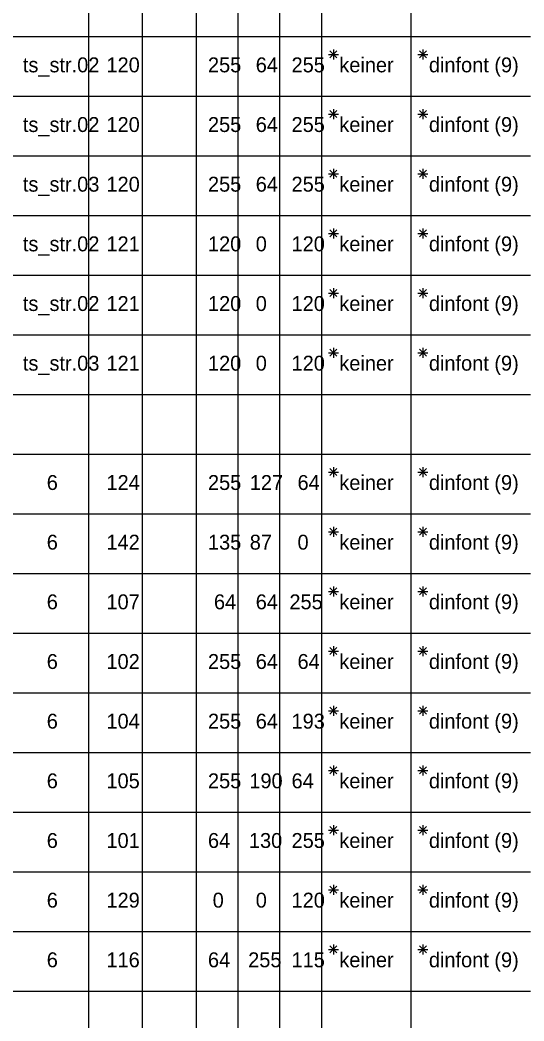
# Model space of a CAD drawing. Extents: x -29 to 48, y -113 to 16.
# Drawn here: x 23.45 to 31.89, y -47.5 to -30.72 of the extents above; entities that cross this region are included whole.
import ezdxf

# ---------------------------------------------------------------- set-up
doc = ezdxf.new("R2010")
doc.units = 0
doc.layers.add('Default', color=7, linetype='Continuous')

msp = doc.modelspace()

# ---------------------------------------------------------------- linework, layer by layer
at = {"layer": 'Default'}
for p, q in [((24.6, -0.7), (24.6, -89)), ((25.5, -0.7), (25.5, -89)), ((26.4, -0.7), (26.4, -89)), ((28.5, -0.7), (28.5, -96)), ((30, -0.7), (30, -96)), ((27.1, -1.5), (27.1, -89)), ((27.8, -1.5), (27.8, -89)), ((0, -31), (32, -31)), ((28.616, -31.3), (28.784, -31.3)), ((28.641, -31.241), (28.759, -31.359)), ((28.759, -31.241), (28.641, -31.359)), ((28.7, -31.216), (28.7, -31.384)), ((30.116, -31.3), (30.284, -31.3)), ((30.141, -31.241), (30.259, -31.359)), ((30.259, -31.241), (30.141, -31.359)), ((30.2, -31.216), (30.2, -31.384)), ((0, -32), (32, -32)), ((28.616, -32.3), (28.784, -32.3)), ((28.641, -32.241), (28.759, -32.359)), ((28.759, -32.241), (28.641, -32.359)), ((28.7, -32.216), (28.7, -32.384)), ((30.116, -32.3), (30.284, -32.3)), ((30.141, -32.241), (30.259, -32.359)), ((30.259, -32.241), (30.141, -32.359)), ((30.2, -32.216), (30.2, -32.384)), ((0, -33), (32, -33)), ((28.7, -33.216), (28.7, -33.384)), ((30.2, -33.216), (30.2, -33.384)), ((28.616, -33.3), (28.784, -33.3)), ((28.641, -33.241), (28.759, -33.359)), ((28.759, -33.241), (28.641, -33.359)), ((30.116, -33.3), (30.284, -33.3)), ((30.141, -33.241), (30.259, -33.359)), ((30.259, -33.241), (30.141, -33.359)), ((0, -34), (32, -34)), ((28.7, -34.216), (28.7, -34.384)), ((30.2, -34.216), (30.2, -34.384)), ((28.616, -34.3), (28.784, -34.3)), ((28.641, -34.241), (28.759, -34.359)), ((28.759, -34.241), (28.641, -34.359)), ((30.116, -34.3), (30.284, -34.3)), ((30.141, -34.241), (30.259, -34.359)), ((30.259, -34.241), (30.141, -34.359)), ((0, -35), (32, -35)), ((28.7, -35.216), (28.7, -35.384)), ((30.2, -35.216), (30.2, -35.384)), ((28.616, -35.3), (28.784, -35.3)), ((28.641, -35.241), (28.759, -35.359)), ((28.759, -35.241), (28.641, -35.359)), ((30.116, -35.3), (30.284, -35.3)), ((30.141, -35.241), (30.259, -35.359)), ((30.259, -35.241), (30.141, -35.359)), ((0, -36), (32, -36)), ((28.7, -36.216), (28.7, -36.384)), ((30.2, -36.216), (30.2, -36.384)), ((28.616, -36.3), (28.784, -36.3)), ((28.641, -36.241), (28.759, -36.359)), ((28.759, -36.241), (28.641, -36.359)), ((30.116, -36.3), (30.284, -36.3)), ((30.141, -36.241), (30.259, -36.359)), ((30.259, -36.241), (30.141, -36.359)), ((0, -37), (32, -37)), ((0, -38), (32, -38)), ((28.641, -38.241), (28.759, -38.359)), ((28.759, -38.241), (28.641, -38.359)), ((28.7, -38.216), (28.7, -38.384)), ((30.141, -38.241), (30.259, -38.359)), ((30.259, -38.241), (30.141, -38.359)), ((30.2, -38.216), (30.2, -38.384)), ((28.616, -38.3), (28.784, -38.3)), ((30.116, -38.3), (30.284, -38.3)), ((0, -39), (32, -39)), ((28.641, -39.241), (28.759, -39.359)), ((28.759, -39.241), (28.641, -39.359)), ((28.7, -39.216), (28.7, -39.384)), ((30.141, -39.241), (30.259, -39.359)), ((30.259, -39.241), (30.141, -39.359)), ((30.2, -39.216), (30.2, -39.384)), ((28.616, -39.3), (28.784, -39.3)), ((30.116, -39.3), (30.284, -39.3)), ((0, -40), (32, -40)), ((28.641, -40.241), (28.759, -40.359)), ((28.759, -40.241), (28.641, -40.359)), ((28.7, -40.216), (28.7, -40.384)), ((30.141, -40.241), (30.259, -40.359)), ((30.259, -40.241), (30.141, -40.359)), ((30.2, -40.216), (30.2, -40.384)), ((28.616, -40.3), (28.784, -40.3)), ((30.116, -40.3), (30.284, -40.3)), ((0, -41), (32, -41)), ((28.641, -41.241), (28.759, -41.359)), ((28.759, -41.241), (28.641, -41.359)), ((28.7, -41.216), (28.7, -41.384)), ((30.141, -41.241), (30.259, -41.359)), ((30.259, -41.241), (30.141, -41.359)), ((30.2, -41.216), (30.2, -41.384)), ((28.616, -41.3), (28.784, -41.3)), ((30.116, -41.3), (30.284, -41.3)), ((0, -42), (32, -42)), ((28.641, -42.241), (28.759, -42.359)), ((28.759, -42.241), (28.641, -42.359)), ((28.7, -42.216), (28.7, -42.384)), ((30.141, -42.241), (30.259, -42.359)), ((30.259, -42.241), (30.141, -42.359)), ((30.2, -42.216), (30.2, -42.384)), ((28.616, -42.3), (28.784, -42.3)), ((30.116, -42.3), (30.284, -42.3)), ((0, -43), (32, -43)), ((28.641, -43.241), (28.759, -43.359)), ((28.759, -43.241), (28.641, -43.359)), ((28.7, -43.216), (28.7, -43.384)), ((30.141, -43.241), (30.259, -43.359)), ((30.259, -43.241), (30.141, -43.359)), ((30.2, -43.216), (30.2, -43.384)), ((28.616, -43.3), (28.784, -43.3)), ((30.116, -43.3), (30.284, -43.3)), ((0, -44), (32, -44)), ((28.641, -44.241), (28.759, -44.359)), ((28.759, -44.241), (28.641, -44.359)), ((28.7, -44.216), (28.7, -44.384)), ((30.141, -44.241), (30.259, -44.359)), ((30.259, -44.241), (30.141, -44.359)), ((30.2, -44.216), (30.2, -44.384)), ((28.616, -44.3), (28.784, -44.3)), ((30.116, -44.3), (30.284, -44.3)), ((0, -45), (32, -45)), ((28.641, -45.241), (28.759, -45.359)), ((28.759, -45.241), (28.641, -45.359)), ((28.7, -45.216), (28.7, -45.384)), ((30.141, -45.241), (30.259, -45.359)), ((30.259, -45.241), (30.141, -45.359)), ((30.2, -45.216), (30.2, -45.384)), ((28.616, -45.3), (28.784, -45.3)), ((30.116, -45.3), (30.284, -45.3)), ((0, -46), (32, -46)), ((28.616, -46.3), (28.784, -46.3)), ((28.641, -46.241), (28.759, -46.359)), ((28.759, -46.241), (28.641, -46.359)), ((28.7, -46.216), (28.7, -46.384)), ((30.116, -46.3), (30.284, -46.3)), ((30.141, -46.241), (30.259, -46.359)), ((30.259, -46.241), (30.141, -46.359)), ((30.2, -46.216), (30.2, -46.384)), ((0, -47), (32, -47))]:
    msp.add_line(p, q, dxfattribs=at)

# ---------------------------------------------------------------- texts
for s, p in [('ts_str.02', (23.5, -31.6)), ('120', (24.9, -31.6)), ('255', (26.6, -31.6)), ('64', (27.4, -31.6)), ('255', (28, -31.6)), ('keiner', (28.8, -31.6)), ('dinfont (9)', (30.3, -31.6)), ('ts_str.02', (23.5, -32.6)), ('120', (24.9, -32.6)), ('255', (26.6, -32.6)), ('64', (27.4, -32.6)), ('255', (28, -32.6)), ('keiner', (28.8, -32.6)), ('dinfont (9)', (30.3, -32.6)), ('ts_str.03', (23.5, -33.6)), ('120', (24.9, -33.6)), ('255', (26.6, -33.6)), ('64', (27.4, -33.6)), ('255', (28, -33.6)), ('keiner', (28.8, -33.6)), ('dinfont (9)', (30.3, -33.6)), ('ts_str.02', (23.5, -34.6)), ('121', (24.9, -34.6)), ('120', (26.6, -34.6)), ('0', (27.4, -34.6)), ('120', (28, -34.6)), ('keiner', (28.8, -34.6)), ('dinfont (9)', (30.3, -34.6)), ('ts_str.02', (23.5, -35.6)), ('121', (24.9, -35.6)), ('120', (26.6, -35.6)), ('0', (27.4, -35.6)), ('120', (28, -35.6)), ('keiner', (28.8, -35.6)), ('dinfont (9)', (30.3, -35.6)), ('ts_str.03', (23.5, -36.6)), ('121', (24.9, -36.6)), ('120', (26.6, -36.6)), ('0', (27.4, -36.6)), ('120', (28, -36.6)), ('keiner', (28.8, -36.6)), ('dinfont (9)', (30.3, -36.6)), ('6', (23.9, -38.6)), ('124', (24.9, -38.6)), ('255', (26.6, -38.6)), ('127', (27.3, -38.6)), ('64', (28.1, -38.6)), ('keiner', (28.8, -38.6)), ('dinfont (9)', (30.3, -38.6)), ('6', (23.9, -39.6)), ('142', (24.9, -39.6)), ('135', (26.6, -39.6)), ('87', (27.3, -39.6)), ('0', (28.1, -39.6)), ('keiner', (28.8, -39.6)), ('dinfont (9)', (30.3, -39.6)), ('6', (23.9, -40.6)), ('107', (24.9, -40.6)), ('64', (26.7, -40.6)), ('64', (27.4, -40.6)), ('255', (27.964, -40.6)), ('keiner', (28.8, -40.6)), ('dinfont (9)', (30.3, -40.6)), ('6', (23.9, -41.6)), ('102', (24.9, -41.6)), ('255', (26.6, -41.6)), ('64', (27.4, -41.6)), ('64', (28.1, -41.6)), ('keiner', (28.8, -41.6)), ('dinfont (9)', (30.3, -41.6)), ('6', (23.9, -42.6)), ('104', (24.9, -42.6)), ('255', (26.6, -42.6)), ('64', (27.4, -42.6)), ('193', (28, -42.6)), ('keiner', (28.8, -42.6)), ('dinfont (9)', (30.3, -42.6)), ('6', (23.9, -43.6)), ('105', (24.9, -43.6)), ('255', (26.6, -43.6)), ('190', (27.293, -43.6)), ('64', (28, -43.6)), ('keiner', (28.8, -43.6)), ('dinfont (9)', (30.3, -43.6)), ('6', (23.9, -44.6)), ('101', (24.9, -44.6)), ('64', (26.6, -44.6)), ('130', (27.286, -44.6)), ('255', (28, -44.6)), ('keiner', (28.8, -44.6)), ('dinfont (9)', (30.3, -44.6)), ('6', (23.9, -45.6)), ('129', (24.9, -45.6)), ('0', (26.679, -45.6)), ('0', (27.4, -45.6)), ('120', (28, -45.6)), ('keiner', (28.8, -45.6)), ('dinfont (9)', (30.3, -45.6)), ('6', (23.9, -46.6)), ('116', (24.9, -46.6)), ('64', (26.6, -46.6)), ('255', (27.273, -46.6)), ('115', (28, -46.6)), ('keiner', (28.8, -46.6)), ('dinfont (9)', (30.3, -46.6))]:
    msp.add_text(s, height=0.25, dxfattribs=at).set_placement(p)

doc.saveas('drawing.dxf')
